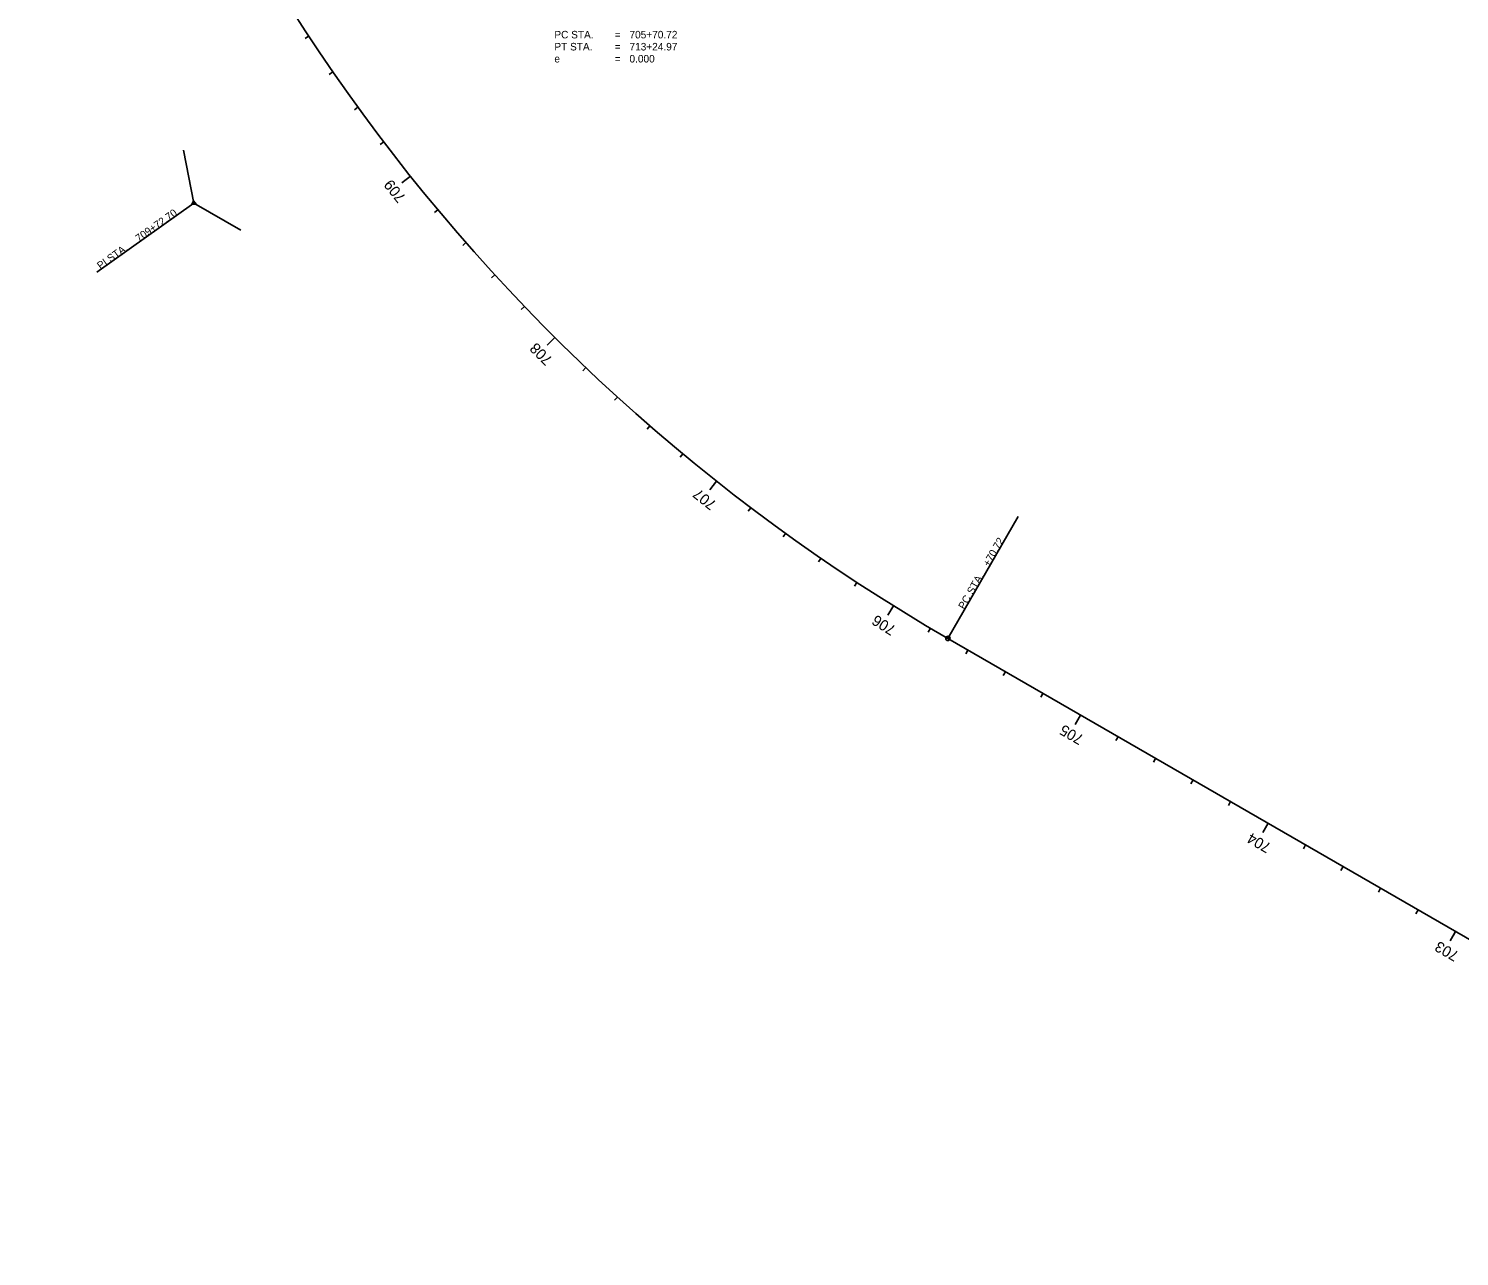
# Model space of a CAD drawing. Extents: x 2005660 to 2007493, y 401364 to 404817.
# Drawn here: x 2005915 to 2006576, y 402643 to 403210 of the extents above; entities that cross this region are included whole.
import ezdxf

# ---------------------------------------------------------------- set-up
doc = ezdxf.new("R2010")
doc.units = 0
for name, color, linetype in [('ConstLines', 7, 'Continuous'), ('PavtAsphalt', 7, 'Continuous'), ('PavtAsphalt_ep', 7, 'Continuous'), ('PavtMilling', 7, 'Continuous'), ('ScratchEle_dp', 7, 'Continuous'), ('SidewalkBack', 7, 'Continuous'), ('SidewalkFront', 7, 'Continuous'), ('TrafSeparator', 7, 'Continuous')]:
    doc.layers.add(name, color=color, linetype=linetype)

msp = doc.modelspace()

# ---------------------------------------------------------------- linework, layer by layer
at = {"layer": 'PavtAsphalt'}
for p, q in [((2006044.31, 403206.65), (2006042.64, 403205.55)), ((2006055.5, 403190.08), (2006053.86, 403188.94)), ((2006067.07, 403173.76), (2006065.45, 403172.59)), ((2006079, 403157.71), (2006077.41, 403156.5)), ((2006091.29, 403141.93), (2006087.38, 403138.82)), ((2006103.94, 403126.44), (2006102.41, 403125.16)), ((2006116.94, 403111.24), (2006115.43, 403109.92)), ((2006130.27, 403096.34), (2006128.8, 403094.99)), ((2006143.95, 403081.74), (2006142.5, 403080.36)), ((2006157.95, 403067.46), (2006154.42, 403063.92)), ((2006172.27, 403053.5), (2006170.89, 403052.05)), ((2006186.9, 403039.87), (2006185.56, 403038.39)), ((2006201.84, 403026.57), (2006200.53, 403025.06)), ((2006217.08, 403013.62), (2006215.8, 403012.08)), ((2006232.61, 403001.01), (2006229.5, 402997.1)), ((2006248.42, 402988.77), (2006247.21, 402987.17)), ((2006264.5, 402976.88), (2006263.33, 402975.26)), ((2006280.85, 402965.36), (2006279.72, 402963.71)), ((2006297.46, 402954.22), (2006296.36, 402952.54)), ((2006314.31, 402943.45), (2006311.67, 402939.21)), ((2006331.41, 402933.07), (2006330.39, 402931.35)), ((2006348.7, 402923.03), (2006347.7, 402921.3)), ((2006366.02, 402913.03), (2006365.02, 402911.29)), ((2006383.34, 402903.02), (2006382.34, 402901.29)), ((2006400.66, 402893.02), (2006398.16, 402888.69)), ((2006417.98, 402883.02), (2006416.98, 402881.29)), ((2006435.3, 402873.01), (2006434.3, 402871.28)), ((2006452.62, 402863.01), (2006451.62, 402861.28)), ((2006469.94, 402853.01), (2006468.94, 402851.28)), ((2006487.26, 402843.01), (2006484.76, 402838.68)), ((2006504.58, 402833), (2006503.58, 402831.27)), ((2006521.89, 402823), (2006520.89, 402821.27)), ((2006539.21, 402813), (2006538.21, 402811.27)), ((2006556.53, 402803), (2006555.53, 402801.26)), ((2006573.85, 402792.99), (2006571.35, 402788.66))]:
    msp.add_line(p, q, dxfattribs=at)
at = {"layer": 'PavtAsphalt_ep'}
msp.add_line((2006833.64, 402642.95), (2006339.42, 402928.39), dxfattribs=at)
msp.add_arc((2006780.04, 403691.29), 881, 190.93889, 239.99111, dxfattribs=at)
at = {"layer": 'ScratchEle_dp'}
for p, q in [((2006091.29, 403141.93), (2006089.73, 403140.69)), ((2006157.95, 403067.46), (2006156.54, 403066.04)), ((2006232.61, 403001.01), (2006231.37, 402999.45)), ((2006314.31, 402943.45), (2006313.26, 402941.75)), ((2006400.66, 402893.02), (2006398.16, 402888.69)), ((2006487.26, 402843.01), (2006486.26, 402841.28)), ((2006573.85, 402792.99), (2006572.85, 402791.26))]:
    msp.add_line(p, q, dxfattribs=at)
at = {"layer": 'SidewalkFront'}
for p, q in [((2005991.32, 403129.44), (2005986.58, 403153.98)), ((2005991.32, 403129.44), (2005946.53, 403097.53)), ((2005991.32, 403129.44), (2006012.97, 403116.93)), ((2006339.42, 402928.39), (2006371.93, 402984.68))]:
    msp.add_line(p, q, dxfattribs=at)
msp.add_lwpolyline([(2005990.38, 403128.77), (2005992.37, 403128.96), (2005991.21, 403130.58)], close=True, dxfattribs=at)
msp.add_circle((2006339.42, 402928.39), 1, dxfattribs=at)
at = {"layer": 'TrafSeparator'}
for p, q in [((2006157.95, 403067.46), (2006156.54, 403066.04)), ((2006314.31, 402943.45), (2006313.26, 402941.75)), ((2006487.26, 402843.01), (2006486.26, 402841.28))]:
    msp.add_line(p, q, dxfattribs=at)

# ---------------------------------------------------------------- texts
at = {"layer": 'ConstLines'}
msp.add_text('705', height=4.98, rotation=149.99111, dxfattribs=at).set_placement((2006402.57, 402883.26))
at = {"layer": 'PavtMilling'}
for s, rotation, p in [('709', 128.57673, (2006089.49, 403132.17)), ('708', 135.08022, (2006157.29, 403057.53)), ('707', 141.58372, (2006233, 402991.13)), ('706', 148.08721, (2006315.87, 402933.65)), ('705', 149.99111, (2006402.57, 402883.26)), ('704', 149.99111, (2006489.1, 402833.28)), ('703', 149.99111, (2006575.78, 402783.22))]:
    msp.add_text(s, height=4.98, rotation=rotation, dxfattribs=at).set_placement(p)
at = {"layer": 'SidewalkBack'}
for s, p in [('PC STA. ', (2006157.77, 403205.55)), ('= ', (2006185.61, 403205.55)), ('705+70.72', (2006192.44, 403205.55)), ('PT STA. ', (2006157.77, 403199.99)), ('= ', (2006185.61, 403199.99)), ('713+24.97', (2006192.44, 403199.99)), ('e', (2006157.77, 403194.42)), ('= ', (2006185.61, 403194.42)), ('0.000', (2006192.44, 403194.42))]:
    msp.add_text(s, height=3.48, dxfattribs=at).set_placement(p)
at = {"layer": 'SidewalkFront'}
for s, rotation, p in [('709+72.70', 35.465, (2005965.93, 403111.35)), ('PI STA. ', 35.465, (2005948.18, 403098.71)), ('+70.72', 59.99111, (2006358.4, 402961.26)), (' STA. ', 59.99111, (2006350.34, 402947.3)), ('PC', 59.99111, (2006347, 402941.52))]:
    msp.add_text(s, height=3.48, rotation=rotation, dxfattribs=at).set_placement(p)

doc.saveas('drawing.dxf')
